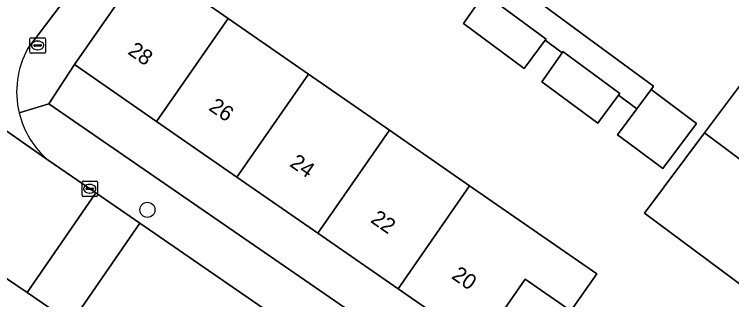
# Model space of a CAD drawing. Extents: x 160023 to 161302, y 384750 to 385707.
# Drawn here: x 160284.79 to 160331.15, y 385154.93 to 385173.4 of the extents above; entities that cross this region are included whole.
import ezdxf

# ---------------------------------------------------------------- set-up
doc = ezdxf.new("R2010")
doc.units = 0
for name, color, linetype in [('IMGEO_Boom', 7, 'Continuous'), ('IMGEO_Erf', 7, 'Continuous'), ('IMGEO_Kolk', 7, 'Continuous'), ('IMGEO_Pand', 7, 'Continuous'), ('IMGEO_Pand_nummerreeks', 7, 'Continuous'), ('IMGEO_Rijbaan_lokaal_gesloten', 7, 'Continuous'), ('IMGEO_Rijbaan_lokaal_open', 7, 'Continuous'), ('IMGEO_Voetpad_open', 7, 'Continuous')]:
    doc.layers.add(name, color=color, linetype=linetype)

msp = doc.modelspace()

# ---------------------------------------------------------------- linework, layer by layer
at = {"layer": 'IMGEO_Boom'}
msp.add_circle((160293.394, 385160.746), 0.489, dxfattribs=at)
at = {"layer": 'IMGEO_Erf'}
for points in [[(160293.316, 385176.811), (160298.616, 385173.131), (160303.803, 385169.53), (160309.029, 385165.901), (160314.216, 385162.299), (160322.429, 385156.597), (160320.768, 385154.206), (160317.81, 385156.259), (160314.845, 385151.989), (160309.591, 385155.637), (160304.403, 385159.239), (160299.178, 385162.868), (160293.991, 385166.469), (160288.691, 385170.149), (160287.026, 385167.6), (160323.304, 385142.564)], [(160318.959, 385174.023), (160321.501, 385172.139), (160326.107, 385168.748), (160325.956, 385168.527), (160328.889, 385166.338), (160326.706, 385163.414), (160324.91, 385164.754), (160323.773, 385165.603), (160325.023, 385167.277), (160323.838, 385168.165), (160322.909, 385166.913), (160322.54, 385166.415), (160322.497, 385166.358), (160318.891, 385169.033), (160320.189, 385170.902), (160319.097, 385171.721), (160317.738, 385169.888), (160313.817, 385172.796), (160315.134, 385174.693)]]:
    msp.add_lwpolyline(points, dxfattribs=at)
msp.add_lwpolyline([(160329.397, 385165.722), (160333.269, 385170.909), (160339.819, 385166.019), (160335.947, 385160.832), (160332.077, 385155.647), (160325.526, 385160.537)], close=True, dxfattribs=at)
at = {"layer": 'IMGEO_Kolk'}
for p, q in [((160285.874, 385171.883), (160286.726, 385171.883)), ((160285.799, 385170.957), (160285.799, 385171.809)), ((160286.058, 385171.377), (160286.058, 385171.389)), ((160286.101, 385171.426), (160286.499, 385171.426)), ((160286.287, 385171.663), (160286.312, 385171.663)), ((160286.542, 385171.389), (160286.542, 385171.377)), ((160286.8, 385171.809), (160286.8, 385170.957)), ((160286.496, 385171.34), (160286.098, 385171.34)), ((160286.31, 385171.103), (160286.285, 385171.103)), ((160286.726, 385170.883), (160285.874, 385170.883)), ((160289.241, 385162.608), (160290.093, 385162.608)), ((160289.166, 385161.682), (160289.166, 385162.534)), ((160289.425, 385162.102), (160289.425, 385162.114)), ((160289.468, 385162.151), (160289.866, 385162.151)), ((160289.654, 385162.388), (160289.679, 385162.388)), ((160289.909, 385162.114), (160289.909, 385162.102)), ((160290.167, 385162.534), (160290.167, 385161.682)), ((160289.863, 385162.065), (160289.465, 385162.065)), ((160289.677, 385161.828), (160289.652, 385161.828)), ((160290.093, 385161.608), (160289.241, 385161.608))]:
    msp.add_line(p, q, dxfattribs=at)
for points in [[(160285.874, 385171.883), (160286.726, 385171.883)], [(160285.799, 385170.957), (160285.799, 385171.809)], [(160286.8, 385171.809), (160286.8, 385170.957)], [(160286.726, 385170.883), (160285.874, 385170.883)], [(160289.241, 385162.608), (160290.093, 385162.608)], [(160289.166, 385161.682), (160289.166, 385162.534)], [(160290.167, 385162.534), (160290.167, 385161.682)], [(160290.093, 385161.608), (160289.241, 385161.608)]]:
    msp.add_lwpolyline(points, dxfattribs=at)
for centre, radius, start, end in [((160285.876, 385171.807), 0.0765, 91.552, 178.448), ((160285.876, 385171.807), 0.0765, 91.552, 178.448), ((160286.724, 385171.807), 0.0765, 1.552, 88.448), ((160286.724, 385171.807), 0.0765, 1.552, 88.448), ((160286.098, 385171.386), 0.0403, 85.8775, 175.7526), ((160286.095, 385171.376), 0.0366, 178.938, 274.7102), ((160286.499, 385171.383), 0.043, 264.8664, 352.4533), ((160286.503, 385171.388), 0.0386, 1.7309, 96.639), ((160285.876, 385170.959), 0.0765, 181.552, 268.448), ((160285.876, 385170.959), 0.0765, 181.552, 268.448), ((160286.724, 385170.959), 0.0765, 271.552, 358.448), ((160286.724, 385170.959), 0.0765, 271.552, 358.448), ((160289.243, 385162.532), 0.0765, 91.552, 178.448), ((160289.243, 385162.532), 0.0765, 91.552, 178.448), ((160290.091, 385162.532), 0.0765, 1.552, 88.448), ((160290.091, 385162.532), 0.0765, 1.552, 88.448), ((160289.465, 385162.111), 0.0403, 85.8775, 175.7526), ((160289.462, 385162.101), 0.0366, 178.938, 274.7102), ((160289.866, 385162.108), 0.043, 264.8664, 352.4533), ((160289.87, 385162.113), 0.0386, 1.7309, 96.639), ((160289.243, 385161.684), 0.0765, 181.552, 268.448), ((160289.243, 385161.684), 0.0765, 181.552, 268.448), ((160290.091, 385161.684), 0.0765, 271.552, 358.448), ((160290.091, 385161.684), 0.0765, 271.552, 358.448)]:
    msp.add_arc(centre, radius, start, end, dxfattribs=at)
for centre, major_axis, ratio, start_param, end_param in [((160286.286, 385171.383), (-0.387, 0.002), 0.722429, 4.712389, 7.853982), ((160286.311, 385171.383), (-0.39, 0.002), 0.717154, 1.570796, 4.712389), ((160289.653, 385162.108), (-0.387, 0.002), 0.722429, 4.712389, 7.853982), ((160289.678, 385162.108), (-0.39, 0.002), 0.717154, 1.570796, 4.712389)]:
    msp.add_ellipse(centre, major_axis=major_axis, ratio=ratio, start_param=start_param, end_param=end_param, dxfattribs=at)
at = {"layer": 'IMGEO_Pand'}
for points in [[(160288.691, 385170.149), (160293.991, 385166.469), (160298.616, 385173.131), (160293.316, 385176.811)], [(160319.097, 385171.721), (160319.156, 385171.8), (160315.176, 385174.753), (160315.134, 385174.693), (160313.817, 385172.796), (160317.738, 385169.888)], [(160293.991, 385166.469), (160299.178, 385162.868), (160303.803, 385169.53), (160298.616, 385173.131)], [(160320.189, 385170.902), (160318.891, 385169.033), (160322.497, 385166.358), (160322.54, 385166.415), (160322.909, 385166.913), (160323.838, 385168.165), (160323.916, 385168.27), (160320.249, 385170.989)], [(160335.947, 385160.832), (160339.819, 385166.019), (160333.269, 385170.909), (160329.397, 385165.722)], [(160309.029, 385165.901), (160303.803, 385169.53), (160299.178, 385162.868), (160304.403, 385159.239)], [(160325.956, 385168.527), (160325.023, 385167.277), (160323.773, 385165.603), (160324.91, 385164.754), (160326.706, 385163.414), (160328.889, 385166.338)], [(160314.216, 385162.299), (160309.029, 385165.901), (160304.403, 385159.239), (160309.591, 385155.637)], [(160329.397, 385165.722), (160325.526, 385160.537), (160332.077, 385155.647), (160335.947, 385160.832)], [(160309.591, 385155.637), (160314.845, 385151.989), (160317.81, 385156.259), (160320.768, 385154.206), (160322.429, 385156.597), (160314.216, 385162.299)]]:
    msp.add_lwpolyline(points, close=True, dxfattribs=at)
at = {"layer": 'IMGEO_Rijbaan_lokaal_gesloten'}
for points in [[(160212.358, 385207.082), (160224.981, 385197.551), (160231.971, 385192.446), (160242.962, 385184.841), (160245.9, 385182.794), (160250.421, 385179.644), (160257.219, 385174.893), (160259.822, 385173.074), (160280.355, 385159.003), (160284.354, 385156.263), (160285.611, 385155.394), (160290.058, 385161.836), (160286.978, 385163.963), (160275.063, 385172.3), (160274.533, 385172.671), (160255.335, 385186.022), (160240.977, 385195.978), (160239.709, 385196.857), (160237.807, 385198.169), (160234.282, 385200.601), (160234.041, 385200.778), (160232.797, 385201.693), (160220.961, 385210.398)], [(160353.245, 385119.896), (160345.516, 385124.585), (160343.306, 385125.926), (160342.253, 385126.595), (160333.972, 385131.862), (160320.265, 385140.909), (160303.373, 385152.644), (160292.906, 385159.87), (160288.457, 385153.426), (160289.202, 385152.911), (160296.619, 385147.784), (160303.129, 385143.274), (160305.222, 385141.852), (160309.156, 385139.136), (160315.869, 385134.573), (160318.091, 385133.105), (160326.434, 385127.602), (160335.598, 385121.727), (160338.966, 385119.621)]]:
    msp.add_lwpolyline(points, dxfattribs=at)
at = {"layer": 'IMGEO_Rijbaan_lokaal_open'}
for points in [[(160285.665, 385171.185), (160307.17, 385199.641), (160330.662, 385231.346)], [(160275.063, 385172.3), (160286.978, 385163.963)]]:
    msp.add_lwpolyline(points, dxfattribs=at)
msp.add_lwpolyline([(160292.906, 385159.87), (160290.058, 385161.836), (160285.611, 385155.394), (160288.457, 385153.426)], close=True, dxfattribs=at)
for centre, radius, start, end in [((160290.744, 385168.379), 5.802, 151.0777, 193.4731), ((160290.739, 385168.374), 5.796, 193.4346, 229.5485)]:
    msp.add_arc(centre, radius, start, end, dxfattribs=at)
at = {"layer": 'IMGEO_Voetpad_open'}
for points in [[(160355.176, 385252.701), (160349.029, 385256.073), (160344.518, 385250), (160330.662, 385231.346), (160307.17, 385199.641), (160285.665, 385171.185)], [(160285.101, 385167.027), (160287.026, 385167.6), (160288.691, 385170.149), (160293.316, 385176.811), (160298.52, 385184.142), (160299.938, 385186.055), (160300.161, 385185.89), (160301.036, 385187.071), (160331.146, 385227.711), (160332.068, 385228.956), (160339.723, 385239.288), (160340.358, 385238.798), (160347.851, 385248.772), (160348.06, 385248.616), (160347.915, 385248.423), (160350.494, 385246.499), (160353.107, 385250), (160354.267, 385251.555), (160355.176, 385252.701)], [(160315.176, 385174.753), (160319.156, 385171.8), (160319.097, 385171.721), (160320.189, 385170.902), (160320.249, 385170.989), (160323.916, 385168.27), (160323.838, 385168.165), (160325.023, 385167.277), (160325.956, 385168.527), (160326.107, 385168.748), (160321.501, 385172.139), (160318.959, 385174.023)], [(160296.619, 385147.784), (160289.202, 385152.911), (160288.457, 385153.426), (160285.611, 385155.394), (160284.354, 385156.263), (160280.355, 385159.003), (160259.822, 385173.074)], [(160287.026, 385167.6), (160285.101, 385167.027)], [(160324.166, 385140.396), (160323.304, 385142.564), (160287.026, 385167.6)], [(160286.978, 385163.963), (160290.058, 385161.836), (160292.906, 385159.87), (160303.373, 385152.644), (160320.265, 385140.909)]]:
    msp.add_lwpolyline(points, dxfattribs=at)
for centre, radius, start, end in [((160290.744, 385168.379), 5.802, 151.0777, 193.4731), ((160290.739, 385168.374), 5.796, 193.4346, 229.5485)]:
    msp.add_arc(centre, radius, start, end, dxfattribs=at)

# ---------------------------------------------------------------- texts
at = {"layer": 'IMGEO_Pand_nummerreeks'}
for s, p in [('28', (160292.067, 385170.872)), ('26', (160297.295, 385167.242)), ('24', (160302.526, 385163.61)), ('22', (160307.755, 385159.98)), ('20', (160312.991, 385156.344))]:
    msp.add_text(s, height=1, rotation=325.2259, dxfattribs=at).set_placement(p)

doc.saveas('drawing.dxf')
